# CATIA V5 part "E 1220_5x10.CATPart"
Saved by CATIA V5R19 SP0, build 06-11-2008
Definition: E 1220_5x10
Nomenclature: E 1220_5x10
Description: PART--DESC
Material "Steel": density 7860 kg/m3, Young's modulus 2e+11 Pa, Poisson ratio 0.266, thermal expansion 1.17e-05 1/K
Bounding box of the stored display mesh (mm): x -309 to -299, y -179.99 to -170.01, z -277.5 to -267.5
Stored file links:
  G:\UTB\Kombinované\Bakalářská práce\Catia\FORMA\E 1220_5x10.CATPart
  D:\Aplikace\CATIA\Nová složka\win_b64\startup\materials\Catalog.CATMaterial
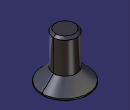
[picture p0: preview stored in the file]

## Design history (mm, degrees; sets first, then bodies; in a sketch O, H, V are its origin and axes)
Body1 "E 1220_5x10" (main body)
  Solid1: solid without history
